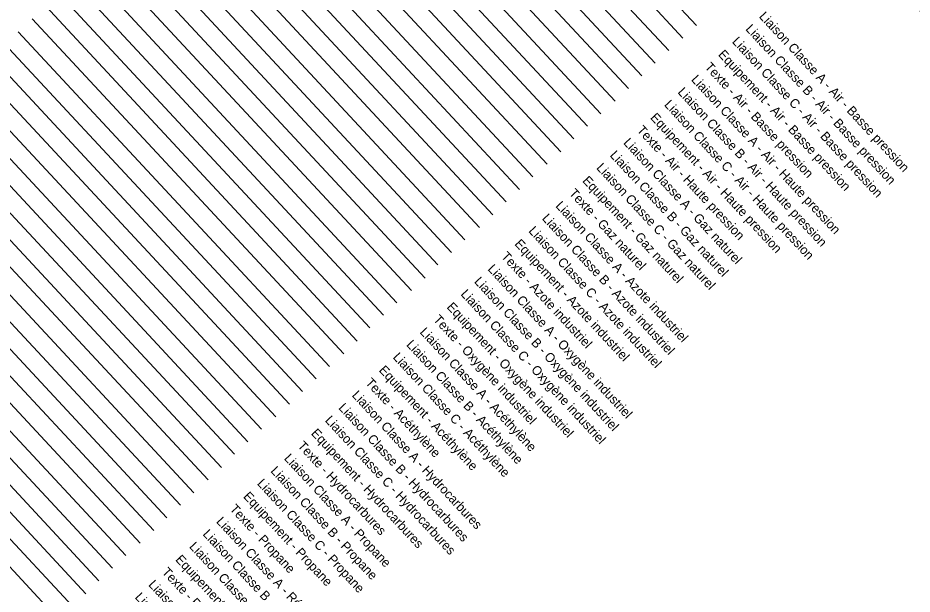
# Model space of a CAD drawing. Extents: x 704383 to 706615, y 7057567 to 7059313.
# Drawn here: x 706378.48 to 706427.03, y 7057678.1 to 7057709.38 of the extents above; entities that cross this region are included whole.
import ezdxf

# ---------------------------------------------------------------- set-up
doc = ezdxf.new("R2010")
doc.units = 0
for name, color, linetype in [('R_ELEC_IST_ALT_POINT', 7, 'Continuous'), ('R_ELEC_IST_POSTE', 7, 'Continuous'), ('R_IND_ACETYLENE_CANALISATION_CL_A', 7, 'Continuous'), ('R_IND_ACETYLENE_CANALISATION_CL_B', 7, 'Continuous'), ('R_IND_ACETYLENE_CANALISATION_CL_C', 7, 'Continuous'), ('R_IND_ACETYLENE_EQUIP', 7, 'Continuous'), ('R_IND_ACETYLENE_TEXTE', 7, 'Continuous'), ('R_IND_AIR_BP_CANALISATION_CL_A', 7, 'Continuous'), ('R_IND_AIR_BP_CANALISATION_CL_B', 7, 'Continuous'), ('R_IND_AIR_BP_CANALISATION_CL_C', 7, 'Continuous'), ('R_IND_AIR_BP_EQUIP', 7, 'Continuous'), ('R_IND_AIR_BP_TEXTE', 7, 'Continuous'), ('R_IND_AIR_HP_CANALISATION_CL_A', 7, 'Continuous'), ('R_IND_AIR_HP_CANALISATION_CL_B', 7, 'Continuous'), ('R_IND_AIR_HP_CANALISATION_CL_C', 7, 'Continuous'), ('R_IND_AIR_HP_EQUIP', 7, 'Continuous'), ('R_IND_AIR_HP_TEXTE', 7, 'Continuous'), ('R_IND_ALT_POINT', 7, 'Continuous'), ('R_IND_AZOTE_CANALISATION_CL_A', 7, 'Continuous'), ('R_IND_AZOTE_CANALISATION_CL_B', 7, 'Continuous'), ('R_IND_AZOTE_CANALISATION_CL_C', 7, 'Continuous'), ('R_IND_AZOTE_EQUIP', 7, 'Continuous'), ('R_IND_AZOTE_TEXTE', 7, 'Continuous'), ('R_IND_EAU_DEMINERALISEE_CANALISATION_CL_A', 7, 'Continuous'), ('R_IND_EAU_DEMINERALISEE_CANALISATION_CL_B', 7, 'Continuous'), ('R_IND_EAU_DEMINERALISEE_CANALISATION_CL_C', 7, 'Continuous'), ('R_IND_EAU_DEMINERALISEE_EQUIP', 7, 'Continuous'), ('R_IND_EAU_DEMINERALISEE_TEXTE', 7, 'Continuous'), ('R_IND_GAZ_NAT_CANALISATION_CL_A', 7, 'Continuous'), ('R_IND_GAZ_NAT_CANALISATION_CL_B', 7, 'Continuous'), ('R_IND_GAZ_NAT_CANALISATION_CL_C', 7, 'Continuous'), ('R_IND_GAZ_NAT_EQUIP', 7, 'Continuous'), ('R_IND_GAZ_NAT_TEXTE', 7, 'Continuous'), ('R_IND_HYDROCARBURE_CANALISATION_CL_A', 7, 'Continuous'), ('R_IND_HYDROCARBURE_CANALISATION_CL_B', 7, 'Continuous'), ('R_IND_HYDROCARBURE_CANALISATION_CL_C', 7, 'Continuous'), ('R_IND_HYDROCARBURE_EQUIP', 7, 'Continuous'), ('R_IND_HYDROCARBURE_TEXTE', 7, 'Continuous'), ('R_IND_INDUS_INCON_CANALISATION_CL_A', 7, 'Continuous'), ('R_IND_INDUS_INCON_CANALISATION_CL_B', 7, 'Continuous'), ('R_IND_INDUS_INCON_CANALISATION_CL_C', 7, 'Continuous'), ('R_IND_INDUS_INCON_EQUIP', 7, 'Continuous'), ('R_IND_INDUS_INCON_TEXTE', 7, 'Continuous'), ('R_IND_OXYGENE_CANALISATION_CL_A', 7, 'Continuous'), ('R_IND_OXYGENE_CANALISATION_CL_B', 7, 'Continuous'), ('R_IND_OXYGENE_CANALISATION_CL_C', 7, 'Continuous'), ('R_IND_OXYGENE_EQUIP', 7, 'Continuous'), ('R_IND_OXYGENE_TEXTE', 7, 'Continuous'), ('R_IND_PROPANE_CANALISATION_CL_A', 7, 'Continuous'), ('R_IND_PROPANE_CANALISATION_CL_B', 7, 'Continuous'), ('R_IND_PROPANE_CANALISATION_CL_C', 7, 'Continuous'), ('R_IND_PROPANE_EQUIP', 7, 'Continuous'), ('R_IND_PROPANE_TEXTE', 7, 'Continuous')]:
    doc.layers.add(name, color=color, linetype=linetype)

msp = doc.modelspace()

# ---------------------------------------------------------------- linework, layer by layer
at = {"layer": 'R_IND_ACETYLENE_CANALISATION_CL_A'}
msp.add_line((706382.19, 7057712.053), (706399.063, 7057693.917), dxfattribs=at)
at = {"layer": 'R_IND_ACETYLENE_CANALISATION_CL_B'}
msp.add_line((706381.458, 7057711.372), (706398.331, 7057693.236), dxfattribs=at)
at = {"layer": 'R_IND_ACETYLENE_CANALISATION_CL_C'}
msp.add_line((706380.726, 7057710.691), (706397.598, 7057692.555), dxfattribs=at)
at = {"layer": 'R_IND_ACETYLENE_EQUIP'}
msp.add_line((706379.994, 7057710.01), (706396.906, 7057691.831), dxfattribs=at)
at = {"layer": 'R_IND_ACETYLENE_TEXTE'}
msp.add_line((706379.262, 7057709.328), (706396.174, 7057691.15), dxfattribs=at)
at = {"layer": 'R_IND_AIR_BP_EQUIP'}
msp.add_line((706398.411, 7057727.144), (706415.324, 7057708.965), dxfattribs=at)
at = {"layer": 'R_IND_AIR_BP_TEXTE'}
msp.add_line((706397.679, 7057726.463), (706414.592, 7057708.284), dxfattribs=at)
at = {"layer": 'R_IND_AIR_HP_CANALISATION_CL_A'}
msp.add_line((706396.924, 7057725.76), (706413.817, 7057707.603), dxfattribs=at)
at = {"layer": 'R_IND_AIR_HP_CANALISATION_CL_B'}
msp.add_line((706396.192, 7057725.079), (706413.084, 7057706.922), dxfattribs=at)
at = {"layer": 'R_IND_AIR_HP_CANALISATION_CL_C'}
msp.add_line((706395.46, 7057724.398), (706412.352, 7057706.241), dxfattribs=at)
at = {"layer": 'R_IND_AIR_HP_EQUIP'}
msp.add_line((706394.728, 7057723.717), (706411.64, 7057705.538), dxfattribs=at)
at = {"layer": 'R_IND_AIR_HP_TEXTE'}
msp.add_line((706393.996, 7057723.036), (706410.908, 7057704.857), dxfattribs=at)
at = {"layer": 'R_IND_ALT_POINT'}
msp.add_line((706363.773, 7057694.919), (706380.686, 7057676.74), dxfattribs=at)
at = {"layer": 'R_IND_AZOTE_CANALISATION_CL_A'}
msp.add_line((706389.557, 7057718.907), (706406.45, 7057700.749), dxfattribs=at)
at = {"layer": 'R_IND_AZOTE_CANALISATION_CL_B'}
msp.add_line((706388.825, 7057718.226), (706405.718, 7057700.068), dxfattribs=at)
at = {"layer": 'R_IND_AZOTE_CANALISATION_CL_C'}
msp.add_line((706388.093, 7057717.544), (706404.985, 7057699.387), dxfattribs=at)
at = {"layer": 'R_IND_AZOTE_EQUIP'}
msp.add_line((706387.361, 7057716.863), (706404.273, 7057698.684), dxfattribs=at)
at = {"layer": 'R_IND_AZOTE_TEXTE'}
msp.add_line((706386.629, 7057716.182), (706403.541, 7057698.003), dxfattribs=at)
at = {"layer": 'R_IND_EAU_DEMINERALISEE_CANALISATION_CL_A'}
msp.add_line((706367.457, 7057698.346), (706384.349, 7057680.188), dxfattribs=at)
at = {"layer": 'R_IND_EAU_DEMINERALISEE_CANALISATION_CL_B'}
msp.add_line((706366.724, 7057697.664), (706383.617, 7057679.507), dxfattribs=at)
at = {"layer": 'R_IND_EAU_DEMINERALISEE_CANALISATION_CL_C'}
msp.add_line((706365.992, 7057696.983), (706382.885, 7057678.826), dxfattribs=at)
at = {"layer": 'R_IND_EAU_DEMINERALISEE_EQUIP'}
msp.add_line((706365.26, 7057696.302), (706382.173, 7057678.123), dxfattribs=at)
at = {"layer": 'R_IND_EAU_DEMINERALISEE_TEXTE'}
msp.add_line((706364.528, 7057695.621), (706381.441, 7057677.442), dxfattribs=at)
at = {"layer": 'R_IND_GAZ_NAT_CANALISATION_CL_A'}
msp.add_line((706393.241, 7057722.334), (706410.133, 7057704.176), dxfattribs=at)
at = {"layer": 'R_IND_GAZ_NAT_CANALISATION_CL_B'}
msp.add_line((706392.509, 7057721.652), (706409.401, 7057703.495), dxfattribs=at)
at = {"layer": 'R_IND_GAZ_NAT_CANALISATION_CL_C'}
msp.add_line((706391.776, 7057720.971), (706408.669, 7057702.814), dxfattribs=at)
at = {"layer": 'R_IND_GAZ_NAT_EQUIP'}
msp.add_line((706391.044, 7057720.29), (706407.957, 7057702.111), dxfattribs=at)
at = {"layer": 'R_IND_GAZ_NAT_TEXTE'}
msp.add_line((706390.312, 7057719.609), (706407.225, 7057701.43), dxfattribs=at)
at = {"layer": 'R_IND_HYDROCARBURE_CANALISATION_CL_A'}
msp.add_line((706378.507, 7057708.626), (706395.409, 7057690.458), dxfattribs=at)
at = {"layer": 'R_IND_HYDROCARBURE_CANALISATION_CL_B'}
msp.add_line((706377.775, 7057707.945), (706394.677, 7057689.777), dxfattribs=at)
at = {"layer": 'R_IND_HYDROCARBURE_CANALISATION_CL_C'}
msp.add_line((706377.043, 7057707.264), (706393.945, 7057689.096), dxfattribs=at)
at = {"layer": 'R_IND_HYDROCARBURE_EQUIP'}
msp.add_line((706376.311, 7057706.583), (706393.223, 7057688.404), dxfattribs=at)
at = {"layer": 'R_IND_HYDROCARBURE_TEXTE'}
msp.add_line((706375.578, 7057705.902), (706392.491, 7057687.723), dxfattribs=at)
at = {"layer": 'R_IND_INDUS_INCON_CANALISATION_CL_A'}
msp.add_line((706371.14, 7057701.772), (706388.043, 7057683.604), dxfattribs=at)
at = {"layer": 'R_IND_INDUS_INCON_CANALISATION_CL_B'}
msp.add_line((706370.408, 7057701.091), (706387.31, 7057682.923), dxfattribs=at)
at = {"layer": 'R_IND_INDUS_INCON_CANALISATION_CL_C'}
msp.add_line((706369.676, 7057700.41), (706386.578, 7057682.242), dxfattribs=at)
at = {"layer": 'R_IND_INDUS_INCON_EQUIP'}
msp.add_line((706368.944, 7057699.729), (706385.856, 7057681.55), dxfattribs=at)
at = {"layer": 'R_IND_INDUS_INCON_TEXTE'}
msp.add_line((706368.211, 7057699.048), (706385.124, 7057680.869), dxfattribs=at)
at = {"layer": 'R_IND_OXYGENE_CANALISATION_CL_A'}
msp.add_line((706385.874, 7057715.48), (706402.756, 7057697.333), dxfattribs=at)
at = {"layer": 'R_IND_OXYGENE_CANALISATION_CL_B'}
msp.add_line((706385.142, 7057714.799), (706402.024, 7057696.652), dxfattribs=at)
at = {"layer": 'R_IND_OXYGENE_CANALISATION_CL_C'}
msp.add_line((706384.41, 7057714.118), (706401.292, 7057695.971), dxfattribs=at)
at = {"layer": 'R_IND_OXYGENE_EQUIP'}
msp.add_line((706383.677, 7057713.436), (706400.59, 7057695.258), dxfattribs=at)
at = {"layer": 'R_IND_OXYGENE_TEXTE'}
msp.add_line((706382.945, 7057712.755), (706399.858, 7057694.576), dxfattribs=at)
at = {"layer": 'R_IND_PROPANE_CANALISATION_CL_A'}
msp.add_line((706374.824, 7057705.199), (706391.706, 7057687.053), dxfattribs=at)
at = {"layer": 'R_IND_PROPANE_CANALISATION_CL_B'}
msp.add_line((706374.091, 7057704.518), (706390.974, 7057686.372), dxfattribs=at)
at = {"layer": 'R_IND_PROPANE_CANALISATION_CL_C'}
msp.add_line((706373.359, 7057703.837), (706390.242, 7057685.69), dxfattribs=at)
at = {"layer": 'R_IND_PROPANE_EQUIP'}
msp.add_line((706372.627, 7057703.156), (706389.54, 7057684.977), dxfattribs=at)
at = {"layer": 'R_IND_PROPANE_TEXTE'}
msp.add_line((706371.895, 7057702.475), (706388.807, 7057684.296), dxfattribs=at)

# ---------------------------------------------------------------- texts
at = {"layer": 'R_ELEC_IST_ALT_POINT'}
msp.add_text('Points et altitudes - Réseaux électriques IST', height=0.5, rotation=312.9332, dxfattribs=at).set_placement((706424.272, 7057714.582))
at = {"layer": 'R_ELEC_IST_POSTE'}
msp.add_text('Poste de transformation - Réseaux électriques IST', height=0.5, rotation=312.9332, dxfattribs=at).set_placement((706423.54, 7057713.901))
at = {"layer": 'R_IND_ACETYLENE_CANALISATION_CL_A'}
msp.add_text('Liaison Classe A - Acéthylène', height=0.5, rotation=312.9332, dxfattribs=at).set_placement((706400.273, 7057692.295))
at = {"layer": 'R_IND_ACETYLENE_CANALISATION_CL_B'}
msp.add_text('Liaison Classe B - Acéthylène', height=0.5, rotation=312.9332, dxfattribs=at).set_placement((706399.541, 7057691.614))
at = {"layer": 'R_IND_ACETYLENE_CANALISATION_CL_C'}
msp.add_text('Liaison Classe C - Acéthylène', height=0.5, rotation=312.9332, dxfattribs=at).set_placement((706398.809, 7057690.933))
at = {"layer": 'R_IND_ACETYLENE_EQUIP'}
msp.add_text('Equipement - Acéthylène', height=0.5, rotation=312.9332, dxfattribs=at).set_placement((706398.054, 7057690.23))
at = {"layer": 'R_IND_ACETYLENE_TEXTE'}
msp.add_text('Texte - Acéthylène', height=0.5, rotation=312.9332, dxfattribs=at).set_placement((706397.322, 7057689.549))
at = {"layer": 'R_IND_AIR_BP_CANALISATION_CL_A'}
msp.add_text('Liaison Classe A - Air - Basse pression', height=0.5, rotation=312.9332, dxfattribs=at).set_placement((706418.69, 7057709.429))
at = {"layer": 'R_IND_AIR_BP_CANALISATION_CL_B'}
msp.add_text('Liaison Classe B - Air - Basse pression', height=0.5, rotation=312.9332, dxfattribs=at).set_placement((706417.958, 7057708.748))
at = {"layer": 'R_IND_AIR_BP_CANALISATION_CL_C'}
msp.add_text('Liaison Classe C - Air - Basse pression', height=0.5, rotation=312.9332, dxfattribs=at).set_placement((706417.226, 7057708.067))
at = {"layer": 'R_IND_AIR_BP_EQUIP'}
msp.add_text('Equipement - Air - Basse pression', height=0.5, rotation=312.9332, dxfattribs=at).set_placement((706416.471, 7057707.364))
at = {"layer": 'R_IND_AIR_BP_TEXTE'}
msp.add_text('Texte - Air - Basse pression', height=0.5, rotation=312.9332, dxfattribs=at).set_placement((706415.739, 7057706.683))
at = {"layer": 'R_IND_AIR_HP_CANALISATION_CL_A'}
msp.add_text('Liaison Classe A - Air - Haute pression', height=0.5, rotation=312.9332, dxfattribs=at).set_placement((706415.007, 7057706.002))
at = {"layer": 'R_IND_AIR_HP_CANALISATION_CL_B'}
msp.add_text('Liaison Classe B - Air - Haute pression', height=0.5, rotation=312.9332, dxfattribs=at).set_placement((706414.275, 7057705.321))
at = {"layer": 'R_IND_AIR_HP_CANALISATION_CL_C'}
msp.add_text('Liaison Classe C - Air - Haute pression', height=0.5, rotation=312.9332, dxfattribs=at).set_placement((706413.543, 7057704.64))
at = {"layer": 'R_IND_AIR_HP_EQUIP'}
msp.add_text('Equipement - Air - Haute pression', height=0.5, rotation=312.9332, dxfattribs=at).set_placement((706412.788, 7057703.938))
at = {"layer": 'R_IND_AIR_HP_TEXTE'}
msp.add_text('Texte - Air - Haute pression', height=0.5, rotation=312.9332, dxfattribs=at).set_placement((706412.056, 7057703.256))
at = {"layer": 'R_IND_AZOTE_CANALISATION_CL_A'}
msp.add_text('Liaison Classe A - Azote industriel', height=0.5, rotation=312.9332, dxfattribs=at).set_placement((706407.64, 7057699.149))
at = {"layer": 'R_IND_AZOTE_CANALISATION_CL_B'}
msp.add_text('Liaison Classe B - Azote industriel', height=0.5, rotation=312.9332, dxfattribs=at).set_placement((706406.908, 7057698.467))
at = {"layer": 'R_IND_AZOTE_CANALISATION_CL_C'}
msp.add_text('Liaison Classe C - Azote industriel', height=0.5, rotation=312.9332, dxfattribs=at).set_placement((706406.176, 7057697.786))
at = {"layer": 'R_IND_AZOTE_EQUIP'}
msp.add_text('Equipement - Azote industriel', height=0.5, rotation=312.9332, dxfattribs=at).set_placement((706405.421, 7057697.084))
at = {"layer": 'R_IND_AZOTE_TEXTE'}
msp.add_text('Texte - Azote industriel', height=0.5, rotation=312.9332, dxfattribs=at).set_placement((706404.689, 7057696.403))
at = {"layer": 'R_IND_EAU_DEMINERALISEE_CANALISATION_CL_A'}
msp.add_text('Liaison Classe A - Eau industrielle déminéralisée', height=0.5, rotation=312.9332, dxfattribs=at).set_placement((706385.539, 7057678.587))
at = {"layer": 'R_IND_EAU_DEMINERALISEE_CANALISATION_CL_B'}
msp.add_text('Liaison Classe B - Eau industrielle déminéralisée', height=0.5, rotation=312.9332, dxfattribs=at).set_placement((706384.807, 7057677.906))
at = {"layer": 'R_IND_GAZ_NAT_CANALISATION_CL_A'}
msp.add_text('Liaison Classe A - Gaz naturel', height=0.5, rotation=312.9332, dxfattribs=at).set_placement((706411.323, 7057702.575))
at = {"layer": 'R_IND_GAZ_NAT_CANALISATION_CL_B'}
msp.add_text('Liaison Classe B - Gaz naturel', height=0.5, rotation=312.9332, dxfattribs=at).set_placement((706410.591, 7057701.894))
at = {"layer": 'R_IND_GAZ_NAT_CANALISATION_CL_C'}
msp.add_text('Liaison Classe C - Gaz naturel', height=0.5, rotation=312.9332, dxfattribs=at).set_placement((706409.859, 7057701.213))
at = {"layer": 'R_IND_GAZ_NAT_EQUIP'}
msp.add_text('Equipement - Gaz naturel', height=0.5, rotation=312.9332, dxfattribs=at).set_placement((706409.104, 7057700.511))
at = {"layer": 'R_IND_GAZ_NAT_TEXTE'}
msp.add_text('Texte - Gaz naturel', height=0.5, rotation=312.9332, dxfattribs=at).set_placement((706408.372, 7057699.83))
at = {"layer": 'R_IND_HYDROCARBURE_CANALISATION_CL_A'}
msp.add_text('Liaison Classe A - Hydrocarbures', height=0.5, rotation=312.9332, dxfattribs=at).set_placement((706396.59, 7057688.868))
at = {"layer": 'R_IND_HYDROCARBURE_CANALISATION_CL_B'}
msp.add_text('Liaison Classe B - Hydrocarbures', height=0.5, rotation=312.9332, dxfattribs=at).set_placement((706395.858, 7057688.187))
at = {"layer": 'R_IND_HYDROCARBURE_CANALISATION_CL_C'}
msp.add_text('Liaison Classe C - Hydrocarbures', height=0.5, rotation=312.9332, dxfattribs=at).set_placement((706395.125, 7057687.506))
at = {"layer": 'R_IND_HYDROCARBURE_EQUIP'}
msp.add_text('Equipement - Hydrocarbures', height=0.5, rotation=312.9332, dxfattribs=at).set_placement((706394.371, 7057686.803))
at = {"layer": 'R_IND_HYDROCARBURE_TEXTE'}
msp.add_text('Texte - Hydrocarbures', height=0.5, rotation=312.9332, dxfattribs=at).set_placement((706393.638, 7057686.122))
at = {"layer": 'R_IND_INDUS_INCON_CANALISATION_CL_B'}
msp.add_text('Liaison Classe B - Réseau inconnu ( industriel )', height=0.5, rotation=312.9332, dxfattribs=at).set_placement((706388.491, 7057681.333))
at = {"layer": 'R_IND_INDUS_INCON_CANALISATION_CL_C'}
for s, p in [('Liaison Classe A - Réseau inconnu ( industriel )', (706389.223, 7057682.014)), ('Liaison Classe C - Réseau inconnu ( industriel )', (706387.758, 7057680.652))]:
    msp.add_text(s, height=0.5, rotation=312.9332, dxfattribs=at).set_placement(p)
at = {"layer": 'R_IND_INDUS_INCON_EQUIP'}
msp.add_text('Equipement - Réseau inconnu ( industriel )', height=0.5, rotation=312.9332, dxfattribs=at).set_placement((706387.004, 7057679.95))
at = {"layer": 'R_IND_INDUS_INCON_TEXTE'}
msp.add_text('Texte - Réseau inconnu ( industriel )', height=0.5, rotation=312.9332, dxfattribs=at).set_placement((706386.271, 7057679.269))
at = {"layer": 'R_IND_OXYGENE_CANALISATION_CL_A'}
msp.add_text('Liaison Classe A - Oxygène industriel', height=0.5, rotation=312.9332, dxfattribs=at).set_placement((706403.957, 7057695.722))
at = {"layer": 'R_IND_OXYGENE_CANALISATION_CL_B'}
msp.add_text('Liaison Classe B - Oxygène industriel', height=0.5, rotation=312.9332, dxfattribs=at).set_placement((706403.224, 7057695.041))
at = {"layer": 'R_IND_OXYGENE_CANALISATION_CL_C'}
msp.add_text('Liaison Classe C - Oxygène industriel', height=0.5, rotation=312.9332, dxfattribs=at).set_placement((706402.492, 7057694.359))
at = {"layer": 'R_IND_OXYGENE_EQUIP'}
msp.add_text('Equipement - Oxygène industriel', height=0.5, rotation=312.9332, dxfattribs=at).set_placement((706401.737, 7057693.657))
at = {"layer": 'R_IND_OXYGENE_TEXTE'}
msp.add_text('Texte - Oxygène industriel', height=0.5, rotation=312.9332, dxfattribs=at).set_placement((706401.005, 7057692.976))
at = {"layer": 'R_IND_PROPANE_CANALISATION_CL_A'}
msp.add_text('Liaison Classe A - Propane', height=0.5, rotation=312.9332, dxfattribs=at).set_placement((706392.906, 7057685.441))
at = {"layer": 'R_IND_PROPANE_CANALISATION_CL_B'}
msp.add_text('Liaison Classe B - Propane', height=0.5, rotation=312.9332, dxfattribs=at).set_placement((706392.174, 7057684.76))
at = {"layer": 'R_IND_PROPANE_CANALISATION_CL_C'}
msp.add_text('Liaison Classe C - Propane', height=0.5, rotation=312.9332, dxfattribs=at).set_placement((706391.442, 7057684.079))
at = {"layer": 'R_IND_PROPANE_EQUIP'}
msp.add_text('Equipement - Propane', height=0.5, rotation=312.9332, dxfattribs=at).set_placement((706390.687, 7057683.377))
at = {"layer": 'R_IND_PROPANE_TEXTE'}
msp.add_text('Texte - Propane', height=0.5, rotation=312.9332, dxfattribs=at).set_placement((706389.955, 7057682.695))

doc.saveas('drawing.dxf')
